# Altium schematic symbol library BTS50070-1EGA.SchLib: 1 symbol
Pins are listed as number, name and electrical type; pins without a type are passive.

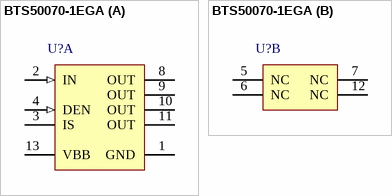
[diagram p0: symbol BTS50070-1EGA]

## BTS50070-1EGA
designator U?
Smart High-Side Power Switch PROFET, 1 Channel, 14 A Load Current, -40 to 150 degC, PG-DSO-12-16, Reel, Green; Manufacturer: Infineon; PartNumber: BTS50070-1EGA; Channels: 1; Green: TRUE; Group: Automotive Qualified; Load Current (typ): 14 A; Recommended Operating Voltage Max.: 28 V; Recommended Operating Voltage Min.: 6 V; RON @ 25degreesC: 7 mOhm; RON(max) @ 150degreesC: 14 mOhm; toff (max): 500 us
footprint INF-PG-DSO-12-16_N (SOP, 12-Leads, Body 7.5x6.4mm, Pitch 1mm, Thermal Pad 4.3X7.9mm, IPC Medium Density)
footprint INF-PG-DSO-12-16_L (SOP, 12-Leads, Body 7.5x6.4mm, Pitch 1mm, Thermal Pad 4.3X7.9mm, IPC High Density)
footprint INF-PG-DSO-12-16_M (SOP, 12-Leads, Body 7.5x6.4mm, Pitch 1mm, Thermal Pad 4.3X7.9mm, IPC Low Density)
part A pins: 1 GND (power) "Ground connection for control chip", 2 IN (in) "Input: activates power switch. Has an internal pull down resistor.", 3 IS (hiz) "Sense Output: With diagnosis enabled, provides a sense current proportional to the load current during normal operation. During open load in ON provides no current. Provides a defined fault current in case of overload, over (See Datasheet)", 4 DEN (in) "Diagnosis ENable: with high level enables diagnosis reporting and open load / short to battery detection in OFF. Resets a protective, latched switch-off by falling edge acknowledgement. Has an internal pull down resistor.", 8 OUT (power) "Output: output to the load; pins 8 to 11 must be externally shorted together", 9 OUT (power) "Output: output to the load; pins 8 to 11 must be externally shorted together", 10 OUT (power) "Output: output to the load; pins 8 to 11 must be externally shorted together", 11 OUT (power) "Output: output to the load; pins 8 to 11 must be externally shorted together", 13 VBB (power) "Supply Voltage: positive power supply for logic and output"
part B pins: 5 NC "Not connected", 6 NC "Not connected", 7 NC "Not connected", 12 NC "Not connected"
